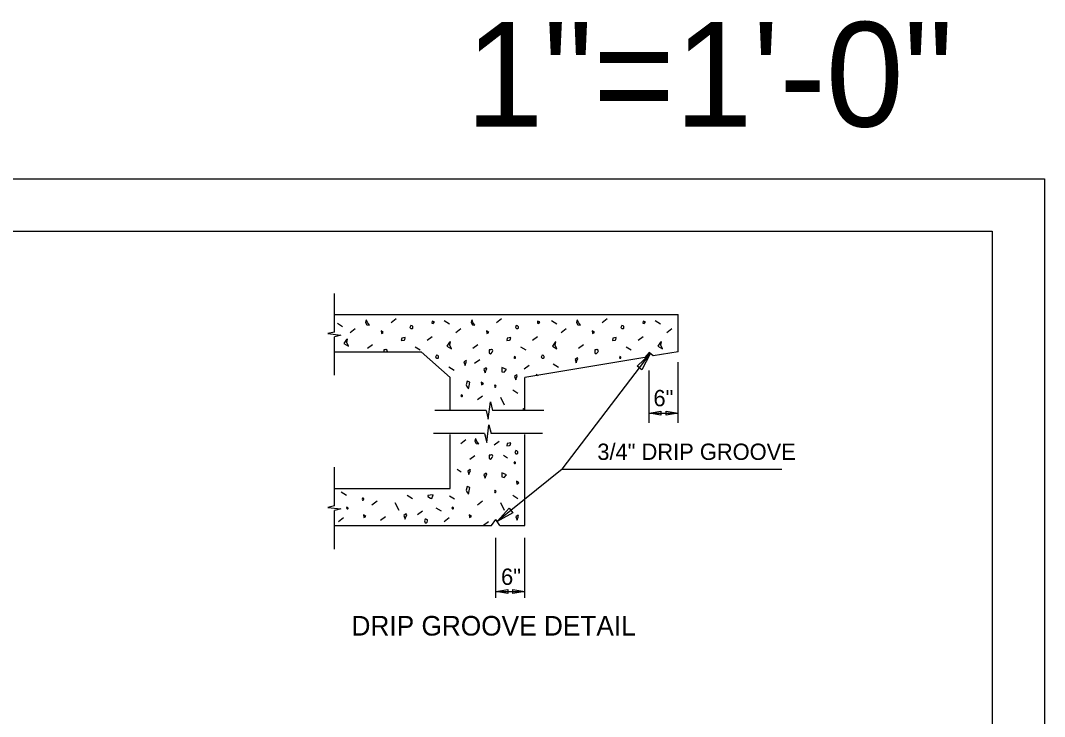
# Model space of a CAD drawing. Extents: x 0 to 34, y 0 to 23.5.
# Drawn here: x 24.21 to 34, y 16.86 to 23.51 of the extents above; entities that cross this region are included whole.
import ezdxf

# ---------------------------------------------------------------- set-up
doc = ezdxf.new("R2010")
doc.units = 0
for name, color, linetype in [('BORDER_ANNO_Cutsheet', 7, 'Continuous'), ('BRDG_ANNO_Anno-Sheet', 7, 'Continuous'), ('BRDG_ANNO_General-Notes', 7, 'Continuous'), ('BRDG_BASE_Obj-Line', 7, 'Continuous'), ('BRDG_BASE_Pattern', 7, 'Continuous')]:
    doc.layers.add(name, color=color, linetype=linetype)

msp = doc.modelspace()

# ---------------------------------------------------------------- linework, layer by layer
at = {"layer": 'BORDER_ANNO_Cutsheet'}
msp.add_lwpolyline([(0, 22), (34, 22), (34, 0), (0, 0)], close=True, dxfattribs=at)
at = {"layer": 'BRDG_ANNO_Anno-Sheet'}
msp.add_lwpolyline([(1.5, 21.5), (33.5, 21.5), (33.5, 0.5), (1.5, 0.5)], close=True, dxfattribs=at)
at = {"layer": 'BRDG_ANNO_General-Notes'}
for p, q in [((29.389, 19.2221), (30.2326, 20.327)), ((30.1062, 20.2084), (30.2326, 20.327)), ((30.2326, 20.327), (30.1515, 20.1737)), ((30.1515, 20.1737), (30.1062, 20.2084)), ((30.22, 19.6669), (30.22, 20.1669)), ((30.4971, 19.6669), (30.4971, 20.247)), ((30.22, 19.7576), (30.334, 19.7766)), ((30.334, 19.7766), (30.334, 19.7386)), ((30.3831, 19.7386), (30.3831, 19.7766)), ((30.3831, 19.7766), (30.4971, 19.7576)), ((30.22, 19.7576), (30.4971, 19.7576)), ((30.334, 19.7386), (30.22, 19.7576)), ((30.4971, 19.7576), (30.3831, 19.7386)), ((29.389, 19.2221), (28.769, 18.7212)), ((29.389, 19.2221), (31.4884, 19.2221)), ((28.769, 18.7212), (28.8841, 18.8509)), ((28.9199, 18.8066), (28.769, 18.7212)), ((28.8841, 18.8509), (28.9199, 18.8066)), ((28.7554, 17.9937), (28.7554, 18.5649)), ((29.0325, 17.9937), (29.0325, 18.5649)), ((28.7554, 18.0539), (28.8694, 18.0729)), ((28.7554, 18.0539), (29.0325, 18.0539)), ((28.8694, 18.0348), (28.7554, 18.0539)), ((28.8694, 18.0729), (28.8694, 18.0348)), ((28.9185, 18.0348), (28.9185, 18.0729)), ((28.9185, 18.0729), (29.0325, 18.0539)), ((29.0325, 18.0539), (28.9185, 18.0348))]:
    msp.add_line(p, q, dxfattribs=at)
at = {"layer": 'BRDG_BASE_Obj-Line'}
for p, q in [((27.2131, 20.5349), (27.2131, 20.9021)), ((27.2117, 20.702), (30.4971, 20.702)), ((30.4971, 20.3458), (30.4971, 20.702)), ((27.2131, 20.5349), (27.1506, 20.5193)), ((27.1506, 20.5193), (27.2756, 20.5037)), ((27.2756, 20.5037), (27.2131, 20.4881)), ((27.2131, 20.1209), (27.2131, 20.4881)), ((27.2117, 20.3458), (28.0429, 20.3458)), ((28.32, 20.0986), (28.0429, 20.3458)), ((30.1804, 20.2923), (29.0325, 20.0986)), ((30.22, 20.3405), (30.1804, 20.2924)), ((30.2596, 20.3056), (30.22, 20.3405)), ((30.4971, 20.3458), (30.2596, 20.3057)), ((28.32, 19.7916), (28.32, 20.0986)), ((29.0325, 19.7916), (29.0325, 20.0986)), ((28.6831, 19.7013), (28.7039, 19.868)), ((28.7039, 19.868), (28.7247, 19.7846)), ((28.6622, 19.7846), (28.1727, 19.7846)), ((28.6622, 19.7846), (28.6831, 19.7013)), ((29.2143, 19.7846), (28.7247, 19.7846)), ((28.6692, 19.4798), (28.6901, 19.6465)), ((28.6901, 19.6465), (28.7109, 19.5631)), ((28.6484, 19.5631), (28.1588, 19.5631)), ((28.32, 19.0395), (28.32, 19.5541)), ((28.6484, 19.5631), (28.6692, 19.4798)), ((29.2005, 19.5631), (28.7109, 19.5631)), ((29.0325, 18.6833), (29.0325, 19.5541)), ((27.2131, 18.8735), (27.2131, 19.2407)), ((27.2117, 19.0395), (28.32, 19.0395)), ((27.2131, 18.8735), (27.1506, 18.8579)), ((27.1506, 18.8579), (27.2756, 18.8422)), ((27.2756, 18.8422), (27.2131, 18.8266)), ((27.2131, 18.4594), (27.2131, 18.8266)), ((28.7144, 18.6833), (28.7554, 18.7406)), ((28.7936, 18.6833), (28.7554, 18.7406)), ((27.2117, 18.6833), (28.7144, 18.6833)), ((28.7936, 18.6833), (29.0325, 18.6833))]:
    msp.add_line(p, q, dxfattribs=at)
at = {"layer": 'BRDG_BASE_Pattern'}
for p, q in [((27.803, 20.6606), (27.7549, 20.624)), ((28.8114, 20.6606), (28.7633, 20.624)), ((29.8198, 20.6606), (29.7717, 20.624)), ((27.2421, 20.6205), (27.2916, 20.5893)), ((27.4119, 20.5651), (27.3638, 20.5284)), ((28.2627, 20.6449), (28.3122, 20.6136)), ((28.4203, 20.5651), (28.3722, 20.5284)), ((29.2893, 20.6449), (29.3388, 20.6136)), ((29.4287, 20.5651), (29.3806, 20.5284)), ((30.2794, 20.6449), (30.3289, 20.6136)), ((30.4371, 20.5651), (30.389, 20.5284)), ((28.1468, 20.4904), (28.0986, 20.4537)), ((29.1552, 20.4904), (29.107, 20.4537)), ((30.1635, 20.4904), (30.1154, 20.4537)), ((27.577, 20.4139), (27.5289, 20.3773)), ((27.9838, 20.3943), (28.0333, 20.3631)), ((28.5854, 20.4139), (28.5372, 20.3773)), ((28.9921, 20.3943), (29.0417, 20.3631)), ((29.5938, 20.4139), (29.5456, 20.3773)), ((30.0005, 20.3943), (30.0501, 20.3631)), ((28.6019, 20.2695), (28.5537, 20.2329)), ((28.3081, 20.2007), (28.3576, 20.1696)), ((29.0741, 20.2156), (29.0259, 20.179)), ((29.3043, 20.2311), (29.3537, 20.2001)), ((29.143, 20.1324), (29.1619, 20.1204)), ((28.9179, 19.9826), (28.9673, 19.9514)), ((28.6288, 19.9229), (28.5807, 19.8863)), ((28.8004, 19.9118), (28.837, 19.8383)), ((29.0325, 19.8054), (29.0156, 19.7926)), ((28.4691, 19.5029), (28.4209, 19.4662)), ((28.787, 19.4887), (28.7389, 19.4521)), ((28.5549, 19.3517), (28.5068, 19.3151)), ((28.8278, 19.3565), (28.8681, 19.331)), ((28.387, 19.2224), (28.4245, 19.1988)), ((27.2792, 19.006), (27.3286, 18.9747)), ((27.6204, 18.9156), (27.5723, 18.879)), ((27.792, 18.9045), (27.8286, 18.8309)), ((27.9095, 18.9753), (27.959, 18.944)), ((28.3119, 18.9695), (28.3613, 18.9382)), ((28.6288, 18.9156), (28.5807, 18.879)), ((28.8004, 18.9045), (28.837, 18.8309)), ((28.9179, 18.9753), (28.9673, 18.944)), ((28.0554, 18.8218), (28.0072, 18.7852)), ((28.1828, 18.8545), (28.2323, 18.8232)), ((27.3016, 18.7568), (27.2535, 18.7202)), ((27.7031, 18.7686), (27.655, 18.732)), ((28.31, 18.7568), (28.2619, 18.7202)), ((28.6871, 18.7199), (28.639, 18.6833))]:
    msp.add_line(p, q, dxfattribs=at)
for points in [[(27.5144, 20.6457), (27.5104, 20.6249), (27.5241, 20.6046), (27.5471, 20.6001), (27.5287, 20.6245), (27.5209, 20.6498)], [(27.9434, 20.5986), (27.9341, 20.5784), (27.9449, 20.5671), (27.9582, 20.5671), (27.9636, 20.573), (27.9636, 20.5838), (27.9618, 20.5891), (27.956, 20.5951)], [(28.1464, 20.6402), (28.1455, 20.6204), (28.1574, 20.6177), (28.1689, 20.631)], [(28.5228, 20.6457), (28.5188, 20.6249), (28.5325, 20.6046), (28.5555, 20.6001), (28.5371, 20.6245), (28.5293, 20.6498)], [(28.9518, 20.5986), (28.9425, 20.5784), (28.9533, 20.5671), (28.9666, 20.5671), (28.972, 20.573), (28.972, 20.5838), (28.9702, 20.5891), (28.9644, 20.5951)], [(29.1547, 20.6402), (29.1539, 20.6204), (29.1658, 20.6177), (29.1773, 20.631)], [(29.5312, 20.6457), (29.5271, 20.6249), (29.5409, 20.6046), (29.5639, 20.6001), (29.5455, 20.6245), (29.5377, 20.6498)], [(29.9602, 20.5986), (29.9509, 20.5784), (29.9617, 20.5671), (29.9749, 20.5671), (29.9804, 20.573), (29.9804, 20.5838), (29.9785, 20.5891), (29.9728, 20.5951)], [(30.1631, 20.6402), (30.1622, 20.6204), (30.1742, 20.6177), (30.1857, 20.631)], [(27.3296, 20.4637), (27.3039, 20.4252), (27.3472, 20.3992), (27.3314, 20.4343), (27.3381, 20.4664)], [(27.6586, 20.5467), (27.6623, 20.5208), (27.6808, 20.5319)], [(27.8564, 20.475), (27.8527, 20.453), (27.8785, 20.4567), (27.8858, 20.4603), (27.8895, 20.4824)], [(28.667, 20.5467), (28.6707, 20.5208), (28.6892, 20.5319)], [(28.8648, 20.475), (28.8611, 20.453), (28.8869, 20.4567), (28.8942, 20.4603), (28.8979, 20.4824)], [(29.6754, 20.5467), (29.6791, 20.5208), (29.6976, 20.5319)], [(29.8732, 20.475), (29.8695, 20.453), (29.8953, 20.4567), (29.9026, 20.4603), (29.9063, 20.4824)], [(28.3137, 20.4393), (28.288, 20.4008), (28.3313, 20.3748), (28.3155, 20.4099), (28.3221, 20.442)], [(28.6935, 20.3636), (28.6935, 20.3357), (28.7062, 20.3267), (28.7101, 20.3303), (28.7209, 20.3414), (28.7283, 20.3562), (28.7229, 20.3636), (28.7155, 20.3671), (28.7119, 20.3671), (28.7047, 20.3651)], [(29.3221, 20.4393), (29.2964, 20.4008), (29.3396, 20.3748), (29.3239, 20.4099), (29.3305, 20.442)], [(29.7019, 20.3636), (29.7019, 20.3357), (29.7146, 20.3267), (29.7184, 20.3303), (29.7293, 20.3414), (29.7367, 20.3562), (29.7313, 20.3636), (29.7239, 20.3671), (29.7203, 20.3671), (29.7131, 20.3651)], [(30.3305, 20.4393), (30.3047, 20.4008), (30.348, 20.3748), (30.3322, 20.4099), (30.3389, 20.442)], [(28.1894, 20.3148), (28.1802, 20.2946), (28.191, 20.2834), (28.2042, 20.2834), (28.2096, 20.2893), (28.2096, 20.3001), (28.2078, 20.3054), (28.2021, 20.3113)], [(28.4506, 20.2484), (28.462, 20.2152), (28.462, 20.2188), (28.4768, 20.2558), (28.473, 20.2631)], [(28.9333, 20.2992), (28.9287, 20.2891), (28.9341, 20.2835), (28.9407, 20.2835), (28.9434, 20.2864), (28.9434, 20.2918), (28.9426, 20.2945), (28.9397, 20.2974)], [(29.1978, 20.3148), (29.1885, 20.2946), (29.1994, 20.2834), (29.2126, 20.2834), (29.218, 20.2893), (29.218, 20.3001), (29.2162, 20.3054), (29.2105, 20.3113)], [(29.5138, 20.2728), (29.5252, 20.2396), (29.5252, 20.2431), (29.5399, 20.2802), (29.5362, 20.2875)], [(29.9417, 20.2992), (29.9371, 20.2891), (29.9425, 20.2835), (29.9491, 20.2835), (29.9518, 20.2864), (29.9518, 20.2918), (29.9509, 20.2945), (29.9481, 20.2974)], [(28.6428, 20.1777), (28.6542, 20.1445), (28.6542, 20.1481), (28.6689, 20.1851), (28.6652, 20.1924)], [(28.8141, 20.1953), (28.8123, 20.1557), (28.8362, 20.1502), (28.8593, 20.1769)], [(28.483, 20.0641), (28.4718, 20.0309), (28.4774, 20.0144), (28.494, 19.9922), (28.5014, 20.0217), (28.5069, 20.0549)], [(28.9351, 20.1099), (28.9465, 20.0767), (28.9465, 20.0803), (28.9612, 20.1173), (28.9574, 20.1246)], [(28.616, 20.0544), (28.6197, 20.0286), (28.6382, 20.0397)], [(28.7434, 20.0168), (28.7463, 20.0076), (28.749, 20.0076), (28.7527, 20.0085), (28.7554, 20.0112), (28.7581, 20.0168), (28.7573, 20.0223), (28.7527, 20.0233), (28.7507, 20.0252), (28.7471, 20.0252)], [(28.4267, 19.9332), (28.422, 19.9231), (28.4274, 19.9174), (28.4341, 19.9174), (28.4368, 19.9204), (28.4368, 19.9258), (28.4359, 19.9285), (28.433, 19.9315)], [(28.5593, 19.5104), (28.5553, 19.4896), (28.569, 19.4693), (28.592, 19.4648), (28.5736, 19.4892), (28.5658, 19.5145)], [(28.8648, 19.4677), (28.8611, 19.4456), (28.8869, 19.4493), (28.8942, 19.4529), (28.8979, 19.4751)], [(28.9457, 19.4024), (28.9364, 19.3822), (28.9472, 19.3709), (28.9605, 19.3709), (28.9659, 19.3768), (28.9659, 19.3876), (28.9641, 19.3929), (28.9583, 19.3989)], [(28.6935, 19.3562), (28.6935, 19.3283), (28.7062, 19.3194), (28.7101, 19.323), (28.7209, 19.3341), (28.7283, 19.3489), (28.7229, 19.3562), (28.7155, 19.3598), (28.7119, 19.3598), (28.7047, 19.3578)], [(28.9333, 19.2919), (28.9287, 19.2818), (28.9341, 19.2761), (28.9407, 19.2761), (28.9434, 19.2791), (28.9434, 19.2845), (28.9426, 19.2871), (28.9397, 19.2901)], [(28.4872, 19.2045), (28.4985, 19.1713), (28.4985, 19.1748), (28.5133, 19.2119), (28.5096, 19.2192)], [(28.6428, 19.1704), (28.6542, 19.1372), (28.6542, 19.1407), (28.6689, 19.1778), (28.6652, 19.1851)], [(28.8141, 19.188), (28.8123, 19.1484), (28.8362, 19.1428), (28.8593, 19.1695)], [(28.9531, 19.1068), (28.9568, 19.0809), (28.9753, 19.092)], [(28.483, 19.0567), (28.4718, 19.0236), (28.4774, 19.007), (28.494, 18.9849), (28.5014, 19.0144), (28.5069, 19.0476)], [(28.7434, 19.0095), (28.7463, 19.0003), (28.749, 19.0003), (28.7527, 19.0012), (28.7554, 19.0039), (28.7581, 19.0095), (28.7573, 19.015), (28.7527, 19.0159), (28.7507, 19.0179), (28.7471, 19.0179)], [(27.4793, 18.9364), (27.4822, 18.9272), (27.4848, 18.9272), (27.4886, 18.9281), (27.4913, 18.9308), (27.494, 18.9364), (27.4932, 18.9419), (27.4886, 18.9429), (27.4866, 18.9448), (27.483, 18.9448)], [(28.1283, 18.9739), (28.1062, 18.972), (28.1062, 18.9609), (28.1302, 18.9444), (28.1432, 18.9426), (28.1561, 18.9775)], [(27.3331, 18.8589), (27.3284, 18.8487), (27.3339, 18.8431), (27.3405, 18.8431), (27.3432, 18.846), (27.3432, 18.8515), (27.3423, 18.8541), (27.3394, 18.8571)], [(27.878, 18.7797), (27.8894, 18.7465), (27.8894, 18.7501), (27.9041, 18.787), (27.9004, 18.7944)], [(28.3415, 18.8589), (28.3368, 18.8487), (28.3422, 18.8431), (28.3489, 18.8431), (28.3516, 18.846), (28.3516, 18.8515), (28.3507, 18.8541), (28.3478, 18.8571)], [(27.492, 18.7851), (27.4957, 18.7593), (27.5142, 18.7704)], [(28.0746, 18.728), (28.0805, 18.7095), (28.0858, 18.7095), (28.0933, 18.7114), (28.0987, 18.7167), (28.1041, 18.728), (28.1026, 18.7389), (28.0933, 18.7408), (28.0894, 18.7446), (28.082, 18.7446)], [(28.5004, 18.7851), (28.5041, 18.7593), (28.5226, 18.7704)], [(28.9472, 18.7675), (28.9586, 18.7343), (28.9586, 18.7379), (28.9733, 18.7748), (28.9696, 18.7822)]]:
    msp.add_lwpolyline(points, close=True, dxfattribs=at)
for points in [[(27.7147, 20.3458), (27.7199, 20.3562), (27.7145, 20.3636), (27.7071, 20.3671), (27.7035, 20.3671), (27.6963, 20.3651), (27.6852, 20.3636)], [(27.6852, 20.3636), (27.6852, 20.3458)]]:
    msp.add_lwpolyline(points, dxfattribs=at)

# ---------------------------------------------------------------- texts
at = {"layer": 'BRDG_ANNO_Anno-Sheet'}
msp.add_text('1"=1\'-0"', height=1, dxfattribs=at).set_placement((28.4668, 22.5))
at = {"layer": 'BRDG_ANNO_General-Notes'}
for s, height, p in [('6"', 0.15625, (30.2623, 19.8248)), ('3/4" DRIP GROOVE', 0.15625, (29.726, 19.3116)), ('6"', 0.15625, (28.8058, 18.1163)), ('DRIP GROOVE DETAIL', 0.1875, (27.3766, 17.6316))]:
    msp.add_text(s, height=height, dxfattribs=at).set_placement(p)

doc.saveas('drawing.dxf')
